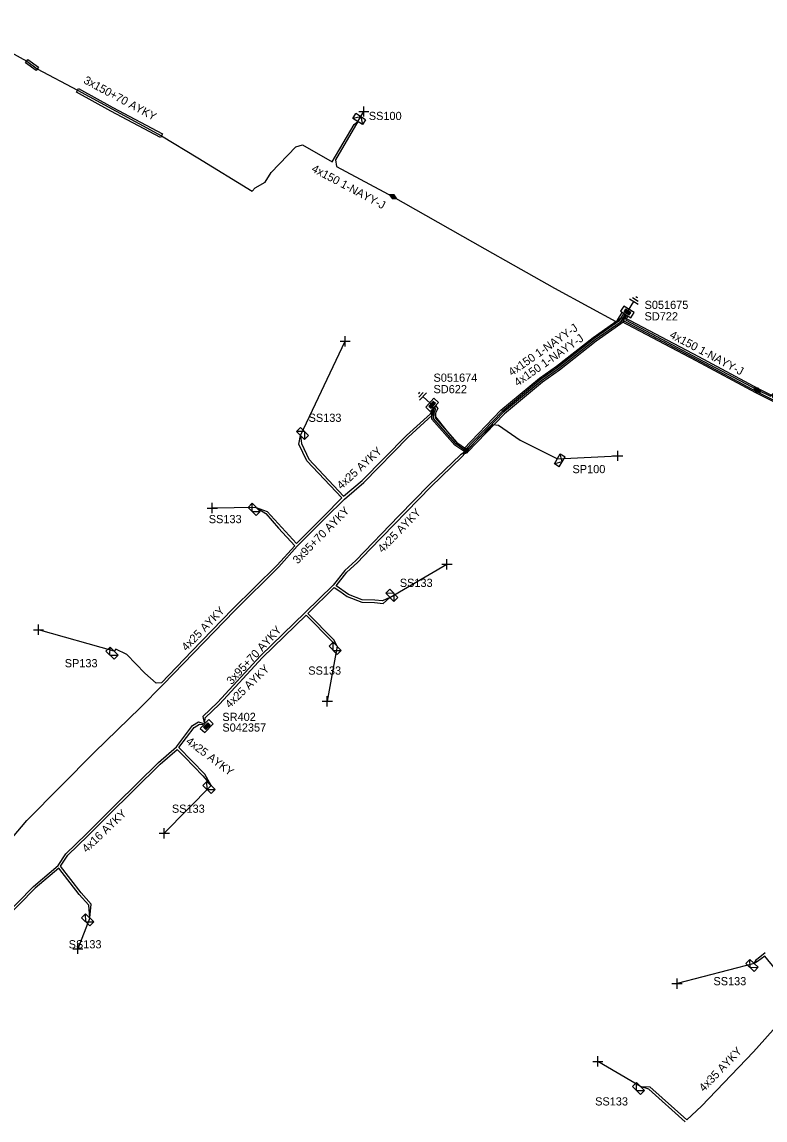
# Model space of a CAD drawing. Extents: x -748492 to -735633, y -1146251 to -1139940.
# Drawn here: x -736528.7 to -736437.9, y -1144300.4 to -1144166.2 of the extents above; entities that cross this region are included whole.
import ezdxf

# ---------------------------------------------------------------- set-up
doc = ezdxf.new("R2010")
doc.units = 0
for name, color, linetype in [('Vrstva 1', 7, 'Continuous'), ('Vrstva 14', 7, 'Continuous'), ('Vrstva 15', 7, 'Continuous'), ('Vrstva 19', 7, 'Continuous'), ('Vrstva 20', 7, 'Continuous'), ('Vrstva 28', 7, 'Continuous'), ('Vrstva 29', 7, 'Continuous'), ('Vrstva 30', 7, 'Continuous'), ('Vrstva 31', 7, 'Continuous'), ('Vrstva 33', 7, 'Continuous'), ('Vrstva 34', 7, 'Continuous'), ('Vrstva 4', 7, 'Continuous'), ('Vrstva 5', 7, 'Continuous'), ('Vrstva 52', 7, 'Continuous'), ('Vrstva 54', 7, 'Continuous'), ('Vrstva 59', 7, 'Continuous'), ('Vrstva 6', 7, 'Continuous'), ('Vrstva 8', 7, 'Continuous'), ('Vrstva 9', 7, 'Continuous')]:
    doc.layers.add(name, color=color, linetype=linetype)

# ---------------------------------------------------------------- blocks, each defined once
blk = doc.blocks.new('NN870')
at = {"layer": 'Vrstva 4'}
for points in [[(0, -0.25), (0.5, 0), (0, 0.25), (-0.5, 0), (0, -0.25)], [(0.37, 0), (0, 0.19), (-0.36, 0), (0, -0.19), (0.37, 0)], [(0.24, 0), (0, 0.12), (-0.25, 0), (0, -0.12), (0.24, 0)], [(0.12, 0), (0, 0.06), (-0.13, 0), (0, -0.06), (0.12, 0)]]:
    blk.add_lwpolyline(points, dxfattribs=at)
blk = doc.blocks.new('NN800')
at = {"layer": 'Vrstva 1'}
for points in [[(-0.44, 0.44), (0.44, -0.44)], [(-0.44, -0.44), (0.44, 0.44)]]:
    blk.add_lwpolyline(points, dxfattribs=at)
blk = doc.blocks.new('NN620')
at = {"layer": 'Vrstva 8'}
for points in [[(0.75, 0), (-0.75, 0)], [(-0.75, 0), (-0.75, -0.75)], [(0.75, -0.75), (0.75, 0)], [(-0.75, -0.75), (0.75, -0.75)], [(0.37, -0.18), (-0.38, -0.18)], [(-0.38, -0.18), (-0.38, -0.56)], [(-0.38, -0.56), (0.37, -0.56)], [(0.32, -0.23), (-0.33, -0.23)], [(-0.33, -0.23), (-0.33, -0.51)], [(-0.33, -0.51), (0.32, -0.51)], [(0.27, -0.27), (-0.28, -0.27)], [(-0.28, -0.27), (-0.28, -0.46)], [(-0.28, -0.46), (0.27, -0.46)], [(0.23, -0.32), (-0.23, -0.32)], [(-0.23, -0.32), (-0.23, -0.42)], [(-0.23, -0.42), (0.23, -0.42)], [(-0.19, -0.37), (0.19, -0.37)], [(0.23, -0.42), (0.23, -0.32)], [(0.27, -0.46), (0.27, -0.27)], [(0.32, -0.51), (0.32, -0.23)], [(0.37, -0.56), (0.37, -0.18)]]:
    blk.add_lwpolyline(points, dxfattribs=at)
blk = doc.blocks.new('NN630')
at = {"layer": 'Vrstva 9'}
for points in [[(0, -0.7), (-0.7, 0)], [(-0.7, -0.7), (-0.7, 0), (0.7, 0), (0.7, -0.7)], [(-0.7, -0.7), (0.7, -0.7)], [(0, -0.7), (0.7, 0)]]:
    blk.add_lwpolyline(points, dxfattribs=at)
blk = doc.blocks.new('NN810')
at = {"layer": 'Vrstva 14'}
for points in [[(0, -0.64), (0, -1.89)], [(0.63, -1.89), (-0.62, -1.89)], [(0.39, -2.2), (-0.4, -2.2)], [(0, -2.52), (-0.12, -2.52)], [(0.14, -2.52), (0, -2.52)]]:
    blk.add_lwpolyline(points, dxfattribs=at)

msp = doc.modelspace()

# ---------------------------------------------------------------- linework, layer by layer
at = {"layer": 'Vrstva 20'}
for points in [[(-736528.28, -1144171.21), (-736527.98, -1144170.81), (-736526.68, -1144171.77), (-736526.98, -1144172.17)], [(-736522.04, -1144174.79), (-736521.8, -1144174.35), (-736517.61, -1144176.68), (-736511.52, -1144179.92), (-736511.76, -1144180.36), (-736517.85, -1144177.12)], [(-736474.7, -1144218.4), (-736470.15, -1144213.67), (-736465.45, -1144209.77), (-736463.36, -1144208.31), (-736458.87, -1144204.77), (-736455.43, -1144202.34), (-736455.09, -1144202.83), (-736458.51, -1144205.25), (-736463, -1144208.79), (-736465.09, -1144210.25), (-736469.73, -1144214.11), (-736474.26, -1144218.82)], [(-736438.71, -1144211.02), (-736429.92, -1144215.47), (-736424.15, -1144218.48), (-736413.18, -1144224.99), (-736413.48, -1144225.51), (-736424.45, -1144219), (-736430.2, -1144216.01), (-736438.99, -1144211.56), (-736446.3, -1144207.66), (-736455.4, -1144202.85), (-736455.12, -1144202.32), (-736446.02, -1144207.12)], [(-736478.2, -1144214.6), (-736475.54, -1144217.64), (-736474.37, -1144218.45), (-736474.59, -1144218.78), (-736475.8, -1144217.94), (-736478.6, -1144214.76), (-736478.62, -1144214.14), (-736478.35, -1144213.53), (-736478.45, -1144213.39), (-736478.13, -1144213.15), (-736477.89, -1144213.47), (-736478.22, -1144214.22)]]:
    msp.add_lwpolyline(points, close=True, dxfattribs=at)
at = {"layer": 'Vrstva 5'}
for points in [[(-736537.2, -1144166.38), (-736536.86, -1144166.23), (-736534.13, -1144167.73), (-736528.13, -1144171.01), (-736526.83, -1144171.97), (-736521.92, -1144174.57), (-736517.2, -1144177.12), (-736511.64, -1144180.14), (-736507.21, -1144182.84), (-736500.55, -1144186.89), (-736500.18, -1144186.49), (-736498.99, -1144185.82), (-736498.23, -1144184.62), (-736495.22, -1144181.49), (-736494.43, -1144181.26), (-736490.77, -1144183.34), (-736488.09, -1144178.75), (-736487.66, -1144178.4)], [(-736487.66, -1144178.4), (-736490.38, -1144183.07), (-736490.26, -1144183.89), (-736483.33, -1144187.59)], [(-736483.33, -1144187.59), (-736482.09, -1144188.29), (-736472.11, -1144193.94), (-736468.66, -1144195.91), (-736463.61, -1144198.78), (-736459.42, -1144201.03), (-736456.1, -1144202.82), (-736455.89, -1144202.68), (-736455.32, -1144201.73)], [(-736455.15, -1144201.83), (-736455.74, -1144202.8), (-736458.75, -1144204.93), (-736463.24, -1144208.47), (-736465.33, -1144209.93), (-736470.01, -1144213.82), (-736474.56, -1144218.55), (-736475.67, -1144217.79), (-736478.4, -1144214.68), (-736478.42, -1144214.18), (-736478.12, -1144213.5), (-736478.29, -1144213.27)], [(-736454.98, -1144201.94), (-736455.59, -1144202.95), (-736458.63, -1144205.09), (-736463.12, -1144208.63), (-736465.21, -1144210.09), (-736469.87, -1144213.96), (-736474.41, -1144218.68)], [(-736454.82, -1144202.04), (-736455.22, -1144202.72), (-736446.21, -1144207.48), (-736438.9, -1144211.38), (-736430.11, -1144215.83), (-736424.35, -1144218.83), (-736413.38, -1144225.34), (-736409.88, -1144227.2), (-736400.54, -1144231.77), (-736395.35, -1144234.41), (-736391.14, -1144236.6), (-736389.09, -1144237.99), (-736383.01, -1144240.58), (-736381.4, -1144240.53), (-736374.43, -1144243.3), (-736362.17, -1144248.26), (-736352.19, -1144251.9)], [(-736454.65, -1144202.15), (-736454.94, -1144202.65), (-736446.11, -1144207.3), (-736438.8, -1144211.2)], [(-736438.8, -1144211.2), (-736437.22, -1144211.96), (-736436.86, -1144211.64), (-736436.99, -1144212.09), (-736430.01, -1144215.65), (-736424.25, -1144218.65), (-736413.29, -1144225.16), (-736413.05, -1144224.72)], [(-736566.72, -1144302.62), (-736563.44, -1144299.17), (-736559.41, -1144295.3), (-736554.26, -1144290.18), (-736551.97, -1144287.53), (-736547.49, -1144283.69), (-736540.63, -1144276.83), (-736536.27, -1144272.28), (-736529.86, -1144265.88), (-736528.1, -1144263.8), (-736519.85, -1144255.47), (-736514.26, -1144250.03), (-736511.43, -1144247.18), (-736502.74, -1144238.2), (-736497.3, -1144232.8), (-736495.05, -1144230.3), (-736491.6, -1144226.83), (-736489.29, -1144224.54), (-736486.92, -1144222.5), (-736481.5, -1144216.99), (-736478.56, -1144214.3), (-736478.23, -1144213.25), (-736478.25, -1144213.23)], [(-736500.08, -1144225.55), (-736498.72, -1144226.04), (-736495.16, -1144229.97), (-736491.82, -1144226.61), (-736489.62, -1144224.39), (-736493.88, -1144219.85), (-736494.85, -1144217.81), (-736494.65, -1144216.78), (-736494.55, -1144217.75), (-736493.62, -1144219.67), (-736489.4, -1144224.2), (-736487.12, -1144222.28), (-736481.7, -1144216.77), (-736478.78, -1144214.1), (-736478.32, -1144213.34), (-736478.34, -1144213.32)], [(-736474.41, -1144218.68), (-736475.08, -1144219.12), (-736478.94, -1144222.81), (-736482.63, -1144226.57), (-736487.9, -1144232.06), (-736489.22, -1144233.25), (-736490.66, -1144235.07), (-736494.08, -1144238.41), (-736499.53, -1144243.7), (-736504.8, -1144249.4), (-736506.6, -1144251.11), (-736506.43, -1144251.88)], [(-736506.34, -1144251.79), (-736506.32, -1144251.25), (-736504.58, -1144249.6), (-736499.31, -1144243.91), (-736493.97, -1144238.74), (-736490.8, -1144241.92), (-736490.18, -1144242.53), (-736490.57, -1144241.72), (-736493.78, -1144238.52), (-736490.53, -1144235.36), (-736489.86, -1144235.77), (-736488.94, -1144236.45), (-736487.17, -1144237.13), (-736485.6, -1144237.19), (-736484.55, -1144237.29), (-736483.75, -1144236.55)], [(-736556.31, -1144301.41), (-736554.45, -1144299.7), (-736549.53, -1144294.6), (-736545.55, -1144290.55), (-736542.71, -1144287.76), (-736536.96, -1144282.09), (-736535.89, -1144280.82), (-736531.22, -1144275.87), (-736527.29, -1144271.87), (-736524.27, -1144269.31), (-736523.36, -1144267.87), (-736520.84, -1144265.48), (-736517.18, -1144261.83), (-736512.03, -1144256.72), (-736509.83, -1144254.82), (-736507.86, -1144252.21), (-736507.12, -1144251.77), (-736506.52, -1144251.98)], [(-736505.59, -1144259.53), (-736506.36, -1144258.14), (-736509.52, -1144254.89), (-736507.66, -1144252.43), (-736507, -1144252.05), (-736506.61, -1144252.07)], [(-736520.43, -1144275.7), (-736520.23, -1144274.04), (-736521.48, -1144272.66), (-736523.98, -1144269.4), (-736523.12, -1144268.07), (-736520.64, -1144265.7), (-736518.19, -1144263.24), (-736511.83, -1144256.94), (-736509.75, -1144255.14), (-736508.81, -1144256.08), (-736506.6, -1144258.34), (-736505.59, -1144259.53)], [(-736436.58, -1144281.98), (-736437.9, -1144280.38), (-736438.79, -1144281.06), (-736439.22, -1144281.27), (-736438.9, -1144280.8), (-736437.86, -1144279.96)], [(-736447.65, -1144300.62), (-736452.08, -1144296.64), (-736453.1, -1144296.31), (-736451.94, -1144296.36), (-736447.45, -1144300.4), (-736445.65, -1144298.74), (-736439.27, -1144292.09), (-736436.19, -1144288.62)]]:
    msp.add_lwpolyline(points, dxfattribs=at)
at = {"layer": 'Vrstva 52'}
for points in [[(-736483.75, -1144236.55), (-736484.63, -1144236.99), (-736485.58, -1144236.89), (-736487.11, -1144236.83), (-736488.8, -1144236.19), (-736490.31, -1144235.13), (-736489, -1144233.45), (-736487.7, -1144232.28), (-736486.19, -1144230.7), (-736478.72, -1144223.03), (-736474.88, -1144219.34), (-736473.32, -1144217.54), (-736471.15, -1144215.44), (-736470.44, -1144215.5), (-736467.81, -1144217.33), (-736463.26, -1144219.62)], [(-736500.08, -1144225.55), (-736498.9, -1144226.28), (-736497.34, -1144228.08), (-736495.36, -1144230.23), (-736497.52, -1144232.6), (-736502.96, -1144237.99), (-736507.93, -1144243.13), (-736511.65, -1144246.98), (-736512.3, -1144247.04), (-736513.7, -1144245.81), (-736515.9, -1144243.52), (-736517.23, -1144242.89), (-736517.45, -1144243.11)], [(-736520.43, -1144275.7), (-736520.53, -1144274.16), (-736521.71, -1144272.86), (-736524.18, -1144269.65), (-736527.09, -1144272.09), (-736531, -1144276.07), (-736535.67, -1144281.02), (-736531.34, -1144285.81), (-736531.25, -1144286.67), (-736531.54, -1144287.25)]]:
    msp.add_lwpolyline(points, dxfattribs=at)
at = {"layer": 'Vrstva 59'}
for points in [[(-736487.66, -1144178.4), (-736486.92, -1144177.17)], [(-736494.65, -1144216.78), (-736489.19, -1144205.25)], [(-736463.26, -1144219.62), (-736455.88, -1144219.25)], [(-736500.08, -1144225.55), (-736505.44, -1144225.63)], [(-736483.75, -1144236.55), (-736476.75, -1144232.5)], [(-736517.45, -1144243.11), (-736526.69, -1144240.5)], [(-736490.18, -1144242.53), (-736491.38, -1144249.25)], [(-736505.59, -1144259.53), (-736511.31, -1144265.38)], [(-736520.43, -1144275.7), (-736521.88, -1144279.5)], [(-736439.22, -1144281.27), (-736448.63, -1144283.75)], [(-736453.1, -1144296.31), (-736458.31, -1144293.25)]]:
    msp.add_lwpolyline(points, dxfattribs=at)
at = {"layer": 'Vrstva 9'}
msp.add_lwpolyline([(-736478.15, -1144213.99), (-736478.16, -1144214.5), (-736476.71, -1144216.27), (-736475.44, -1144217.81)], dxfattribs=at)

# ---------------------------------------------------------------- block references
at = {"layer": 'Vrstva 15'}
for p, rotation in [((-736454.9, -1144201.99), 147.8975888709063), ((-736478.29, -1144213.27), -132.30094991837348)]:
    msp.add_blockref('NN810', p, dxfattribs=dict(at, rotation=rotation))
at = {"layer": 'Vrstva 19'}
for p, rotation in [((-736483.33, -1144187.59), -28.098227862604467), ((-736438.82, -1144211.2), -28.07777501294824), ((-736474.41, -1144218.68), 46.11456391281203)]:
    msp.add_blockref('NN870', p, dxfattribs=dict(at, rotation=rotation))
at = {"layer": 'Vrstva 28'}
for p, rotation in [((-736454.9, -1144201.99), 147.8975888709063), ((-736478.29, -1144213.27), -132.30094996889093), ((-736506.38, -1144252.02), 45.80693049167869)]:
    msp.add_blockref('NN620', p, dxfattribs=dict(at, rotation=rotation))
at = {"layer": 'Vrstva 31'}
for p, rotation in [((-736487.66, -1144178.4), 147.65704170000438), ((-736494.65, -1144216.78), 135.17775273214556), ((-736463.26, -1144219.62), 58.97934723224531), ((-736500.08, -1144225.55), -45.314325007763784), ((-736483.75, -1144236.55), 134.70516947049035), ((-736517.45, -1144243.11), -45.15117507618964), ((-736490.18, -1144242.53), -45.40443327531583), ((-736505.59, -1144259.53), -43.984797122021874), ((-736520.43, -1144275.7), -43.855855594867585), ((-736439.22, -1144281.27), -44.00844170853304), ((-736453.1, -1144296.31), -45.354736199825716)]:
    msp.add_blockref('NN630', p, dxfattribs=dict(at, rotation=rotation))
at = {"layer": 'Vrstva 34'}
for p, rotation in [((-736486.92, -1144177.17), 45), ((-736489.19, -1144205.25), 44.99999995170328), ((-736455.88, -1144219.25), 45), ((-736505.44, -1144225.63), 44.99999995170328), ((-736476.75, -1144232.5), 45), ((-736526.69, -1144240.5), 44.99999995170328), ((-736491.38, -1144249.25), 45), ((-736511.31, -1144265.38), 45), ((-736521.88, -1144279.5), 45), ((-736448.63, -1144283.75), 45), ((-736458.31, -1144293.25), 45)]:
    msp.add_blockref('NN800', p, dxfattribs=dict(at, rotation=rotation))

# ---------------------------------------------------------------- texts
at = {"layer": 'Vrstva 29'}
for s, p in [('S051675', (-736452.6, -1144201.3)), ('S051674', (-736478.4, -1144210.2)), ('S042357', (-736504.21, -1144252.95))]:
    msp.add_text(s, height=1, dxfattribs=at).set_placement(p)
at = {"layer": 'Vrstva 30'}
for s, p in [('SD722', (-736452.6, -1144202.7)), ('SD622', (-736478.4, -1144211.6)), ('SR402', (-736504.21, -1144251.65))]:
    msp.add_text(s, height=1, dxfattribs=at).set_placement(p)
at = {"layer": 'Vrstva 33'}
for s, p in [('SS100', (-736486.31, -1144178.21)), ('SS133', (-736493.67, -1144215.1)), ('SP100', (-736461.41, -1144221.37)), ('SS133', (-736505.87, -1144227.48)), ('SS133', (-736482.52, -1144235.27)), ('SP133', (-736523.48, -1144245.09)), ('SS133', (-736493.71, -1144245.99)), ('SS133', (-736510.38, -1144262.87)), ('SS133', (-736523, -1144279.44)), ('SS133', (-736444.18, -1144283.95)), ('SS133', (-736458.64, -1144298.64))]:
    msp.add_text(s, height=1, dxfattribs=at).set_placement(p)
at = {"layer": 'Vrstva 54'}
for rotation, p in [(45.787, (-736484.63, -1144231.17)), (45.974, (-736508.6, -1144243.17))]:
    msp.add_text('4x25 AYKY', height=1, rotation=rotation, dxfattribs=at).set_placement(p)
at = {"layer": 'Vrstva 6'}
for s, rotation, p in [('3x150+70 AYKY', 331.62, (-736521.27, -1144173.65)), ('4x150 1-NAYY-J', 331.902, (-736493.4, -1144184.46)), ('4x150 1-NAYY-J', 34.924, (-736468.82, -1144209.55)), ('4x150 1-NAYY-J', 331.922, (-736449.62, -1144204.76)), ('4x150 1-NAYY-J', 34.95, (-736468.11, -1144210.81)), ('4x25 AYKY', 42.444, (-736489.67, -1144223.41)), ('3x95+70 AYKY', 45.256, (-736495.01, -1144232.53)), ('3x95+70 AYKY', 47.245, (-736503.08, -1144247.29)), ('4x25 AYKY', 44.03, (-736503.3, -1144250.15)), ('4x25 AYKY', 322.953, (-736508.75, -1144254.31)), ('4x16 AYKY', 43.584, (-736520.8, -1144267.8)), ('4x35 AYKY', 46.187, (-736445.35, -1144297.03))]:
    msp.add_text(s, height=1, rotation=rotation, dxfattribs=at).set_placement(p)

doc.saveas('drawing.dxf')
